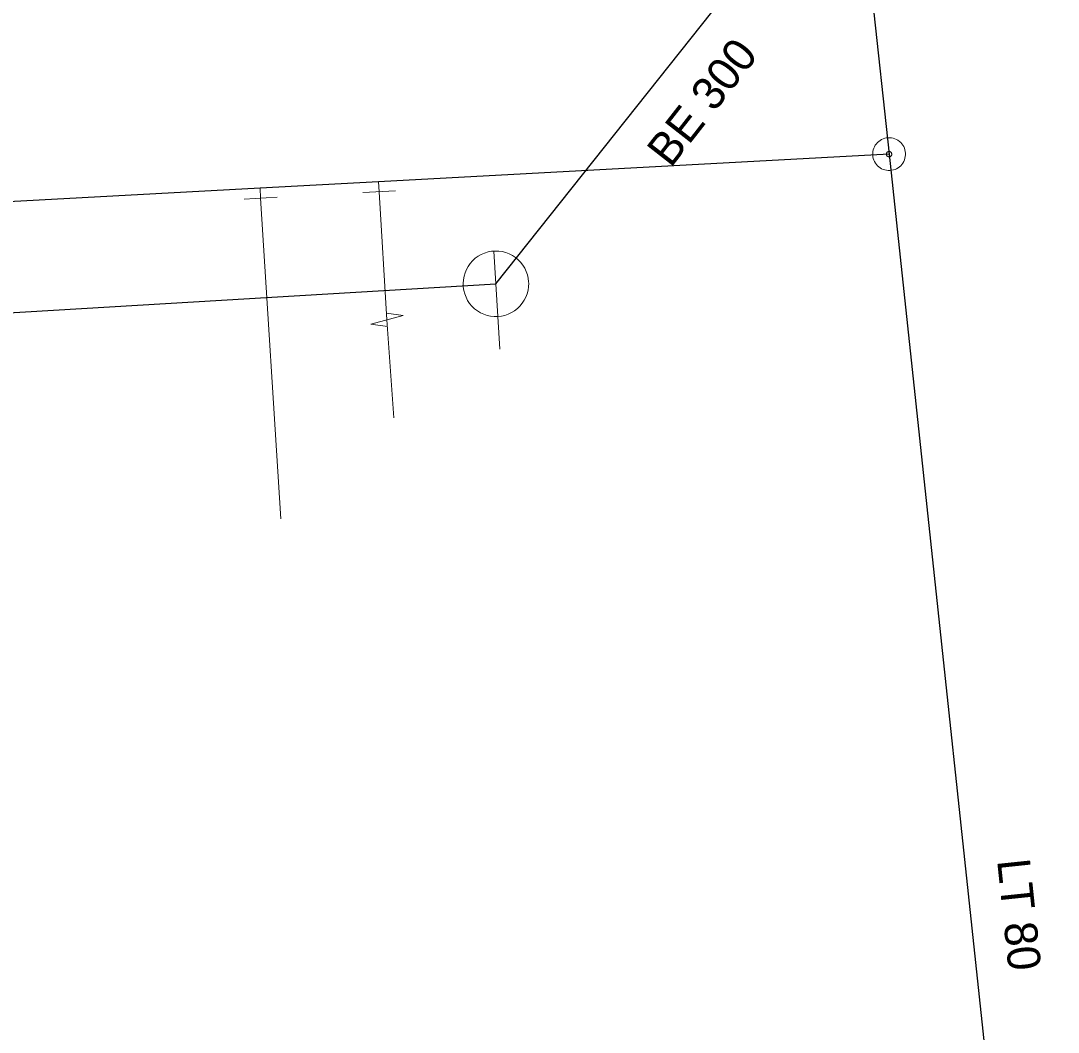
# Model space of a CAD drawing. Extents: x -777996 to -777727, y -976581 to -976199.
# Drawn here: x -777961.28 to -777929.65, y -976257.89 to -976227.07 of the extents above; entities that cross this region are included whole.
import ezdxf

# ---------------------------------------------------------------- set-up
doc = ezdxf.new("R2010")
doc.units = 0
doc.header["$LTSCALE"] = 0.32
doc.linetypes.add('MEDIUM_DASHED', pattern=[4.5, 3, -1.5])
for name, color, linetype, lineweight in [('1', 7, 'MEDIUM_DASHED', 25), ('13', 7, 'Continuous', 13), ('14', 7, 'Continuous', 25), ('17', 7, 'Continuous', 25), ('22', 7, 'Continuous', 13), ('34', 7, 'Continuous', 13), ('47', 7, 'Continuous', 13)]:
    doc.layers.add(name, color=color, linetype=linetype, lineweight=lineweight)

msp = doc.modelspace()

# ---------------------------------------------------------------- linework, layer by layer
at = {"layer": '13'}
msp.add_line((-777953.963, -976232.472), (-777953.351, -976242.25), dxfattribs=at)
msp.add_lwpolyline([(-777950.348, -976232.276), (-777950.112, -976236.181), (-777949.898, -976239.164)], dxfattribs=at)
at = {"layer": '14'}
for p, q in [((-777946.791, -976235.083), (-777935.509, -976220.899)), ((-777994.334, -976237.923), (-777946.791, -976235.083))]:
    msp.add_line(p, q, dxfattribs=at)
at = {"layer": '14', "lineweight": 13}
for p, q in [((-777953.963, -976232.472), (-777953.98, -976232.172)), ((-777950.365, -976231.976), (-777950.348, -976232.276))]:
    msp.add_line(p, q, dxfattribs=at)
at = {"layer": '17'}
msp.add_line((-777935.619, -976223.512), (-777934.804, -976231.131), dxfattribs=at)
for points in [[(-777934.804, -976231.131), (-777950.365, -976231.976), (-777953.98, -976232.172), (-777953.982, -976232.172), (-777968.399, -976232.955), (-777971.795, -976233.14), (-777987.174, -976233.975), (-777988.908, -976234.069), (-777994.444, -976234.369)], [(-777934.804, -976231.131), (-777929.646, -976279.357), (-777933.318, -976282.133), (-777940.43, -976287.506), (-777947.561, -976292.896), (-777957.508, -976300.412), (-777960.673, -976302.804)]]:
    msp.add_lwpolyline(points, dxfattribs=at)
at = {"layer": '22'}
msp.add_line((-777946.671, -976237.079), (-777946.85, -976234.085), dxfattribs=at)
msp.add_lwpolyline([(-777945.792, -976235.023), (-777945.805, -976234.915), (-777945.829, -976234.808), (-777945.865, -976234.704), (-777945.911, -976234.606), (-777945.969, -976234.512), (-777946.036, -976234.426), (-777946.113, -976234.347), (-777946.197, -976234.278), (-777946.289, -976234.218), (-777946.386, -976234.168), (-777946.489, -976234.129), (-777946.596, -976234.103), (-777946.704, -976234.087), (-777946.813, -976234.084), (-777946.923, -976234.092), (-777947.03, -976234.113), (-777947.135, -976234.144), (-777947.236, -976234.187), (-777947.331, -976234.242), (-777947.419, -976234.305), (-777947.501, -976234.379), (-777947.573, -976234.461), (-777947.637, -976234.551), (-777947.69, -976234.646), (-777947.732, -976234.747), (-777947.763, -976234.852), (-777947.783, -976234.96), (-777947.79, -976235.069), (-777947.786, -976235.178), (-777947.769, -976235.287), (-777947.742, -976235.392), (-777947.702, -976235.494), (-777947.652, -976235.591), (-777947.591, -976235.683), (-777947.52, -976235.767), (-777947.441, -976235.842), (-777947.354, -976235.909), (-777947.261, -976235.966), (-777947.162, -976236.012), (-777947.057, -976236.047), (-777946.951, -976236.07), (-777946.842, -976236.082), (-777946.732, -976236.081), (-777946.623, -976236.069), (-777946.517, -976236.044), (-777946.414, -976236.009), (-777946.314, -976235.962), (-777946.22, -976235.904), (-777946.134, -976235.837), (-777946.056, -976235.761), (-777945.986, -976235.677), (-777945.926, -976235.585), (-777945.876, -976235.488), (-777945.838, -976235.386), (-777945.81, -976235.28), (-777945.794, -976235.171), (-777945.791, -976235.061)], close=True, dxfattribs=at)
at = {"layer": '34'}
for p, q in [((-777949.848, -976232.246), (-777950.847, -976232.304)), ((-777953.464, -976232.44), (-777954.462, -976232.502))]:
    msp.add_line(p, q, dxfattribs=at)
at = {"layer": '47'}
msp.add_line((-777949.618, -976236.052), (-777950.124, -976235.98), dxfattribs=at)
for points in [[(-777935.303, -976231.158), (-777935.297, -976231.209), (-777935.286, -976231.261), (-777935.269, -976231.31), (-777935.249, -976231.358), (-777935.222, -976231.404), (-777935.191, -976231.446), (-777935.156, -976231.484), (-777935.117, -976231.519), (-777935.075, -976231.55), (-777935.03, -976231.576), (-777934.981, -976231.598), (-777934.932, -976231.613), (-777934.881, -976231.624), (-777934.828, -976231.63), (-777934.776, -976231.63), (-777934.725, -976231.624), (-777934.673, -976231.613), (-777934.623, -976231.596), (-777934.576, -976231.576), (-777934.53, -976231.549), (-777934.488, -976231.518), (-777934.449, -976231.483), (-777934.414, -976231.444), (-777934.383, -976231.402), (-777934.358, -976231.357), (-777934.336, -976231.308), (-777934.32, -976231.258), (-777934.31, -976231.208), (-777934.304, -976231.155), (-777934.304, -976231.103), (-777934.31, -976231.052), (-777934.321, -976231), (-777934.337, -976230.95), (-777934.358, -976230.903), (-777934.385, -976230.857), (-777934.415, -976230.815), (-777934.45, -976230.776), (-777934.489, -976230.741), (-777934.532, -976230.71), (-777934.577, -976230.685), (-777934.626, -976230.663), (-777934.675, -976230.647), (-777934.726, -976230.637), (-777934.779, -976230.631), (-777934.831, -976230.631), (-777934.882, -976230.637), (-777934.934, -976230.648), (-777934.983, -976230.664), (-777935.031, -976230.685), (-777935.077, -976230.712), (-777935.119, -976230.742), (-777935.157, -976230.777), (-777935.192, -976230.816), (-777935.223, -976230.859), (-777935.249, -976230.904), (-777935.271, -976230.953), (-777935.286, -976231.001), (-777935.297, -976231.053), (-777935.303, -976231.106)], [(-777934.885, -976231.135), (-777934.885, -976231.144), (-777934.882, -976231.152), (-777934.88, -976231.16), (-777934.877, -976231.168), (-777934.872, -976231.175), (-777934.867, -976231.182), (-777934.861, -976231.189), (-777934.855, -976231.194), (-777934.848, -976231.199), (-777934.841, -976231.204), (-777934.832, -976231.207), (-777934.824, -976231.21), (-777934.816, -976231.211), (-777934.808, -976231.213), (-777934.799, -976231.212), (-777934.79, -976231.212), (-777934.782, -976231.209), (-777934.774, -976231.207), (-777934.766, -976231.204), (-777934.759, -976231.199), (-777934.752, -976231.194), (-777934.745, -976231.188), (-777934.74, -976231.182), (-777934.734, -976231.175), (-777934.73, -976231.168), (-777934.727, -976231.159), (-777934.724, -976231.151), (-777934.723, -976231.143), (-777934.721, -976231.135), (-777934.722, -976231.126), (-777934.722, -976231.117), (-777934.725, -976231.109), (-777934.727, -976231.101), (-777934.73, -976231.093), (-777934.735, -976231.086), (-777934.739, -976231.079), (-777934.746, -976231.072), (-777934.752, -976231.067), (-777934.759, -976231.061), (-777934.766, -976231.057), (-777934.775, -976231.054), (-777934.783, -976231.051), (-777934.791, -976231.05), (-777934.799, -976231.048), (-777934.808, -976231.049), (-777934.817, -976231.049), (-777934.825, -976231.052), (-777934.833, -976231.054), (-777934.841, -976231.057), (-777934.848, -976231.062), (-777934.855, -976231.066), (-777934.862, -976231.073), (-777934.867, -976231.079), (-777934.872, -976231.086), (-777934.877, -976231.093), (-777934.88, -976231.102), (-777934.883, -976231.11), (-777934.884, -976231.118), (-777934.886, -976231.126)]]:
    msp.add_lwpolyline(points, close=True, dxfattribs=at)
msp.add_lwpolyline([(-777949.618, -976236.052), (-777950.605, -976236.309), (-777950.099, -976236.381)], dxfattribs=at)

# ---------------------------------------------------------------- texts
at = {"layer": '1'}
for s, rotation, p in [('BE 300', 52, (-777941.463, -976231.575)), ('LT 80 ', 276, (-777931.511, -976252.653))]:
    msp.add_text(s, height=1, rotation=rotation, dxfattribs=at).set_placement(p)

doc.saveas('drawing.dxf')
